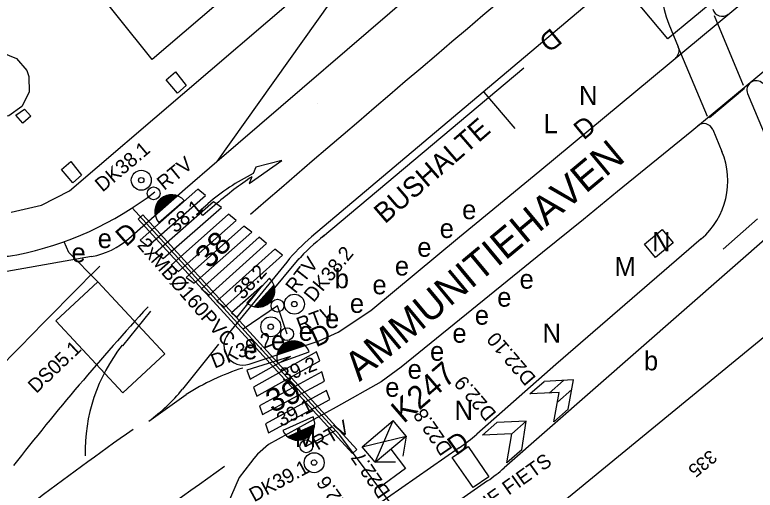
# Model space of a CAD drawing. Extents: x 81617 to 82144, y 454649 to 455150.
# Drawn here: x 81870.9 to 81909.62, y 454868.02 to 454892.85 of the extents above; entities that cross this region are included whole.
import ezdxf

# ---------------------------------------------------------------- set-up
doc = ezdxf.new("R2010")
doc.units = 0
for name, color, linetype in [('B-WE-OG-TOPOGRAFIE-G', 7, 'Continuous'), ('B-WE-VW-MARKERING-G', 7, 'Continuous'), ('N-OI-KL-VRI_KABEL_DETECTIE_SELECTIEF-G', 7, 'Continuous'), ('N-OI-KL-VRI_KABELGEUL-G', 7, 'Continuous'), ('N-OI-KL-VRI_LUS_DETECTIE-G', 7, 'Continuous'), ('N-OI-KL-VRI_LUS_DETECTIE-T18', 7, 'Continuous'), ('N-OI-KL-VRI_LUS_DETECTIE_SELECTIEF-G', 7, 'Continuous'), ('N-OI-KL-VRI_LUS_DETECTIE_SELECTIEF-T18', 7, 'Continuous'), ('N-OI-KL-VRI_MANTELBUIS-G', 7, 'Continuous'), ('N-OI-KL-VRI_MANTELBUIS-T18', 7, 'Continuous'), ('N-WE-VW-VRI_ARMATUUR-S', 7, 'Continuous'), ('N-WE-VW-VRI_ARMATUUR-T18', 7, 'Continuous'), ('N-WE-VW-VRI_KAST-S', 7, 'Continuous'), ('N-WE-VW-VRI_KAST-T25', 7, 'Continuous'), ('N-WE-VW-VRI_MAST-S', 7, 'Continuous'), ('N-WE-VW-VRI_RICHTINGNUMMER-T25', 7, 'Continuous')]:
    doc.layers.add(name, color=color, linetype=linetype)

msp = doc.modelspace()

# ---------------------------------------------------------------- linework, layer by layer
at = {"layer": 'B-WE-OG-TOPOGRAFIE-G'}
for p, q in [((81873.764, 454883.663), (81895.876, 454902.551)), ((81905.057, 454891.588), (81895.876, 454902.551)), ((81915.332, 454900.158), (81905.057, 454891.588)), ((81903.077, 454895.285), (81886.425, 454881.256)), ((81887.412, 454893.525), (81881.465, 454885.191)), ((81905.107, 454892.354), (81905.599, 454891.177)), ((81897.061, 454886.92), (81895.452, 454888.817)), ((81909.22, 454888.733), (81910.638, 454885.336)), ((81907.401, 454886.86), (81907.878, 454885.717)), ((81916.221, 454886.463), (81896.497, 454869.183)), ((81895.714, 454882.526), (81898.36, 454884.706)), ((81872.307, 454882.913), (81873.764, 454883.663)), ((81870.712, 454882.537), (81872.307, 454882.913)), ((81900.642, 454882.153), (81898.504, 454880.427)), ((81874.916, 454880.226), (81869.99, 454879.351)), ((81885.125, 454879.936), (81882.062, 454876.187)), ((81883.151, 454874.605), (81886.811, 454875.821)), ((81894.147, 454870.23), (81885.959, 454864.545))]:
    msp.add_line(p, q, dxfattribs=at)
for points in [[(81905.797, 454910.826), (81895.907, 454902.577), (81894.356, 454904.415), (81878.095, 454890.513), (81872.591, 454897.372), (81877.883, 454901.619), (81888.858, 454911.006), (81888.57, 454911.351)], [(81881.465, 454885.191), (81892.751, 454894.89), (81902.683, 454903.166)], [(81898.36, 454884.706), (81910.134, 454894.484), (81917.589, 454900.632)], [(81919.999, 454898.128), (81906.308, 454886.765), (81902.426, 454883.614), (81900.642, 454882.153)], [(81871.645, 454889.635), (81871.649, 454888.803), (81871.269, 454888.063), (81870.591, 454887.582), (81869.768, 454887.467), (81868.985, 454887.745), (81868.625, 454888.058), (81868.267, 454888.805), (81868.296, 454889.633), (81868.704, 454890.354), (81869.398, 454890.805), (81870.223, 454890.883), (81870.99, 454890.571), (81871.527, 454889.94), (81871.645, 454889.635)], [(81879.871, 454889.153), (81879.407, 454888.757), (81878.816, 454889.449), (81879.303, 454889.864), (81879.871, 454889.153)], [(81871.322, 454887.183), (81870.954, 454887.608), (81871.418, 454887.928), (81871.745, 454887.55), (81871.322, 454887.183)], [(81873.935, 454884.076), (81873.343, 454884.766), (81873.829, 454885.183), (81874.399, 454884.473), (81873.935, 454884.076)], [(81876.866, 454881.167), (81879.804, 454883.764), (81881.465, 454885.191)], [(81886.811, 454875.821), (81887.808, 454876.282), (81889.527, 454877.414), (81894.156, 454881.247), (81895.714, 454882.526)], [(81891.095, 454859.963), (81890.844, 454860.269), (81917.092, 454881.782)], [(81904.758, 454881.628), (81905.336, 454880.933), (81904.402, 454880.175), (81903.833, 454880.868), (81904.758, 454881.628)], [(81906.798, 454881.147), (81899.186, 454874.583), (81895.056, 454870.943)], [(81898.504, 454880.427), (81891.112, 454874.44), (81890.056, 454873.683), (81887.703, 454872.36), (81884.178, 454870.411), (81883.594, 454869.904), (81883.411, 454869.671)], [(81883.411, 454869.671), (81883.233, 454869.443)], [(81883.233, 454869.443), (81882.632, 454868.676), (81882.012, 454867.245), (81881.775, 454865.703), (81881.936, 454864.151), (81882.502, 454862.646)], [(81895.625, 454868.501), (81888.346, 454863.428)]]:
    msp.add_lwpolyline(points, dxfattribs=at)
for centre, radius, start, end in [((81909.721, 454894.281), 5, 129.9068, 202.6584), ((81907.892, 454893.272), 0.5, 194.9072, 309.7087), ((81905.137, 454890.984), 0.5, 309.7087, 22.6584), ((81909.674, 454888.918), 0.491, 45.0027, 202.1804), ((81906.939, 454886.668), 0.5, 22.6584, 129.6922), ((81904.187, 454884.176), 4, 310.7629, 22.6584), ((81874.217, 454884.164), 4, 280.0658, 311.4758), ((81892.868, 454873.608), 10, 130.1148, 140.7468), ((81882.836, 454875.554), 1, 140.7468, 288.3806), ((81888.443, 454878.444), 10, 304.7727, 311.399), ((81889.907, 454876.705), 10, 304.8723, 311.2203)]:
    msp.add_arc(centre, radius, start, end, dxfattribs=at)
at = {"layer": 'B-WE-VW-MARKERING-G'}
for p, q in [((81909.012, 454889.161), (81907.493, 454892.8)), ((81907.118, 454887.538), (81905.599, 454891.177)), ((81886.988, 454881.261), (81897.514, 454890.085)), ((81907.227, 454887.492), (81909.068, 454889.019)), ((81886.718, 454888.22), (81886.719, 454888.22)), ((81909.745, 454882.201), (81907.947, 454880.616)), ((81884.154, 454878.169), (81885.773, 454880.127)), ((81876.555, 454875.556), (81878.025, 454877.377)), ((81881.555, 454875.639), (81879.673, 454873.29)), ((81877.904, 454871.631), (81879.86, 454873.02))]:
    msp.add_line(p, q, dxfattribs=at)
for points in [[(81883.298, 454884.391), (81883.152, 454884.032), (81884.861, 454885.235), (81883.508, 454884.892), (81883.367, 454884.558)], [(81881.463, 454882.991), (81880.734, 454882.366), (81880.539, 454882.594), (81880.994, 454882.984)]]:
    msp.add_lwpolyline(points, dxfattribs=at)
for points in [[(81877.857, 454880.761), (81880.868, 454883.416), (81880.477, 454883.739), (81877.466, 454881.085)], [(81878.666, 454880.115), (81881.711, 454882.782), (81881.3, 454883.087), (81878.254, 454880.42)], [(81879.471, 454879.449), (81882.473, 454882.113), (81882.082, 454882.436), (81879.079, 454879.772)], [(81880.282, 454878.833), (81883.303, 454881.504), (81882.887, 454881.806), (81879.866, 454879.135)], [(81881.06, 454878.207), (81884.069, 454880.909), (81883.679, 454881.234), (81880.671, 454878.532)], [(81881.866, 454877.577), (81884.897, 454880.288), (81884.498, 454880.605), (81881.467, 454877.894)], [(81882.524, 454877.051), (81883.851, 454878.709), (81882.231, 454877.291)], [(81883.556, 454872.939), (81886.855, 454874.78), (81886.688, 454875.248), (81883.388, 454873.407)], [(81883.206, 454873.82), (81885.314, 454875.009), (81883.039, 454874.288)], [(81883.858, 454871.966), (81887.102, 454873.719), (81886.966, 454874.205), (81883.691, 454872.433)], [(81884.172, 454871.01), (81887.372, 454872.755), (81887.204, 454873.223), (81884.005, 454871.478)]]:
    msp.add_lwpolyline(points, close=True, dxfattribs=at)
for centre, radius, start, end in [((82917.127, 453685.631), 1581.531, 129.587403, 130.823582), ((81888.509, 454874.227), 11.54, 116.4593, 130.634), ((81894.5, 454867.798), 20.02, 124.0094, 130.634), ((81894.315, 454872.198), 11.647, 128.3994, 137.9113), ((82219.514, 454535.314), 486.895, 134.97926, 135.80708), ((81983.253, 454780.99), 142.962, 137.48788, 141.84973), ((81883.609, 454869.995), 9.033, 141.7483, 181.1781), ((81886.861, 454861.84), 13.191, 107.8383, 122.0585), ((81872.715, 454878.94), 8.964, 305.3706, 320.9237), ((81999.362, 454697.85), 212.13, 125.19968, 128.77534), ((82436.117, 454084.333), 960.875, 125.226465, 125.740356)]:
    msp.add_arc(centre, radius, start, end, dxfattribs=at)
at = {"layer": 'N-OI-KL-VRI_KABEL_DETECTIE_SELECTIEF-G'}
msp.add_line((81875.251, 454878.904), (81873.737, 454880.443), dxfattribs=at)
at = {"layer": 'N-OI-KL-VRI_KABELGEUL-G'}
msp.add_line((81886.146, 454870.311), (81887.671, 454871.144), dxfattribs=at)
for points in [[(81886.495, 454859.072), (81889.398, 454860.377), (81892.955, 454863.292), (81892.853, 454864.259), (81887.904, 454870.888), (81877.049, 454882.767)], [(81873.737, 454880.443), (81873.478, 454881)], [(81885.144, 454876.171), (81884.639, 454877.657), (81882.841, 454876.423)], [(81890.559, 454870.162), (81891.328, 454869.16), (81889.958, 454868.137)]]:
    msp.add_lwpolyline(points, dxfattribs=at)
for centre, radius, start, end in [((81867.653, 454897.27), 17.281, 281.1951, 307.7159), ((81870.263, 454883.584), 3.35, 223.0627, 282.8439)]:
    msp.add_arc(centre, radius, start, end, dxfattribs=at)
at = {"layer": 'N-OI-KL-VRI_LUS_DETECTIE-G'}
for p, q in [((81897.828, 454873.044), (81898.578, 454873.705)), ((81898.851, 454873.091), (81899.601, 454873.752)), ((81899.273, 454872.609), (81900.024, 454873.27)), ((81899.096, 454871.597), (81899.846, 454872.258)), ((81897.644, 454871.62), (81896.894, 454870.959)), ((81895.36, 454870.889), (81896.11, 454871.55)), ((81893.782, 454869.723), (81894.603, 454870.294)), ((81894.603, 454870.294), (81895.697, 454868.724)), ((81897.417, 454870.134), (81896.628, 454869.442)), ((81894.876, 454868.153), (81893.782, 454869.723)), ((81895.697, 454868.724), (81894.876, 454868.153))]:
    msp.add_line(p, q, dxfattribs=at)
for points in [[(81899.846, 454872.258), (81900.112, 454873.775), (81898.578, 454873.705)], [(81899.096, 454871.597), (81899.362, 454873.114), (81897.828, 454873.044)], [(81897.417, 454870.134), (81897.644, 454871.62), (81896.11, 454871.55)], [(81896.628, 454869.442), (81896.894, 454870.959), (81895.36, 454870.889)]]:
    msp.add_lwpolyline(points, dxfattribs=at)
at = {"layer": 'N-OI-KL-VRI_LUS_DETECTIE_SELECTIEF-G'}
for p, q in [((81875.251, 454878.904), (81873.056, 454876.859)), ((81878.756, 454875.14), (81875.251, 454878.904)), ((81873.056, 454876.859), (81876.561, 454873.096)), ((81876.561, 454873.096), (81878.756, 454875.14))]:
    msp.add_line(p, q, dxfattribs=at)
at = {"layer": 'N-OI-KL-VRI_MANTELBUIS-G'}
msp.add_lwpolyline([(81877.355, 454882.183), (81877.592, 454882.399), (81888.796, 454870.15), (81888.56, 454869.934), (81877.355, 454882.183)], dxfattribs=at)
at = {"layer": 'N-WE-VW-VRI_ARMATUUR-S'}
for p, q in [((81878.226, 454882.575), (81879.225, 454883.442)), ((81878.227, 454882.535), (81879.263, 454883.435)), ((81878.228, 454882.614), (81879.185, 454883.448)), ((81878.23, 454882.499), (81879.301, 454883.428)), ((81878.231, 454882.657), (81879.142, 454883.453)), ((81878.234, 454882.461), (81879.336, 454883.42)), ((81878.235, 454882.702), (81879.098, 454883.452)), ((81878.24, 454882.426), (81879.37, 454883.409)), ((81878.241, 454882.749), (81879.049, 454883.45)), ((81878.247, 454882.393), (81879.401, 454883.397)), ((81878.255, 454882.797), (81879, 454883.445)), ((81878.27, 454882.851), (81878.944, 454883.438)), ((81878.292, 454882.91), (81878.882, 454883.426)), ((81878.322, 454882.976), (81878.812, 454883.402)), ((81878.371, 454883.058), (81878.726, 454883.367)), ((81878.48, 454883.193), (81878.577, 454883.28)), ((81878.441, 454882.004), (81879.759, 454883.153)), ((81884.22, 454879.097), (81883.038, 454877.807)), ((81884.456, 454878.732), (81883.421, 454877.605)), ((81884.466, 454878.699), (81883.454, 454877.596)), ((81884.476, 454878.666), (81883.488, 454877.589)), ((81884.484, 454878.629), (81883.525, 454877.585)), ((81884.492, 454878.593), (81883.563, 454877.582)), ((81884.497, 454878.553), (81883.601, 454877.579)), ((81884.5, 454878.514), (81883.642, 454877.578)), ((81884.502, 454878.472), (81883.686, 454877.578)), ((81884.502, 454878.426), (81883.729, 454877.584)), ((81884.501, 454878.378), (81883.777, 454877.592)), ((81884.493, 454878.329), (81883.825, 454877.602)), ((81884.485, 454878.274), (81883.88, 454877.615)), ((81884.469, 454878.213), (81883.941, 454877.634)), ((81884.446, 454878.144), (81884.007, 454877.666)), ((81884.407, 454878.057), (81884.089, 454877.71)), ((81884.314, 454877.911), (81884.228, 454877.814)), ((81884.616, 454875.085), (81886.058, 454875.598)), ((81884.622, 454875.119), (81886.033, 454875.621)), ((81884.629, 454875.153), (81886.006, 454875.643)), ((81884.639, 454875.19), (81885.976, 454875.664)), ((81884.649, 454875.225), (81885.943, 454875.684)), ((81884.664, 454875.262), (81885.91, 454875.704)), ((81884.679, 454875.298), (81885.875, 454875.725)), ((81884.697, 454875.337), (81885.837, 454875.745)), ((81884.718, 454875.377), (81885.795, 454875.76)), ((81884.741, 454875.419), (81885.749, 454875.776)), ((81884.772, 454875.459), (81885.702, 454875.789)), ((81884.805, 454875.503), (81885.647, 454875.803)), ((81884.848, 454875.55), (81885.585, 454875.815)), ((81884.9, 454875.601), (81885.511, 454875.818)), ((81884.974, 454875.659), (81885.418, 454875.817)), ((81885.126, 454875.745), (81885.247, 454875.79)), ((81884.654, 454874.653), (81886.302, 454875.24)), ((81886.509, 454871.854), (81884.913, 454871.14)), ((81886.581, 454871.426), (81885.184, 454870.802)), ((81886.578, 454871.392), (81885.211, 454870.781)), ((81886.574, 454871.357), (81885.24, 454870.761)), ((81886.566, 454871.32), (81885.271, 454870.742)), ((81886.559, 454871.284), (81885.305, 454870.725)), ((81886.548, 454871.246), (81885.339, 454870.707)), ((81886.535, 454871.208), (81885.377, 454870.69)), ((81886.52, 454871.169), (81885.416, 454870.672)), ((81886.502, 454871.127), (81885.459, 454870.661)), ((81886.482, 454871.083), (81885.506, 454870.649)), ((81886.455, 454871.041), (81885.554, 454870.639)), ((81886.426, 454870.994), (81885.609, 454870.63)), ((81886.387, 454870.944), (81885.673, 454870.623)), ((81886.339, 454870.89), (81885.746, 454870.625)), ((81886.269, 454870.825), (81885.839, 454870.633)), ((81886.125, 454870.728), (81886.007, 454870.673))]:
    msp.add_line(p, q, dxfattribs=at)
for centre, radius in [((81877.519, 454884.21), 0.522), ((81877.514, 454884.214), 0.141), ((81885.524, 454877.735), 0.522), ((81885.519, 454877.738), 0.141), ((81884.292, 454876.552), 0.522), ((81884.287, 454876.555), 0.141), ((81886.556, 454869.456), 0.522), ((81886.551, 454869.459), 0.141)]:
    msp.add_circle(centre, radius, dxfattribs=at)
for centre, start, end in [((81879.1, 454882.578), 41.0181, 221.0181), ((81883.629, 454878.452), 227.456, 47.456), ((81885.478, 454874.946), 19.5786, 199.5786), ((81885.711, 454871.497), 204.0669, 24.0669)]:
    msp.add_arc(centre, 0.873, start, end, dxfattribs=at)
at = {"layer": 'N-WE-VW-VRI_KAST-S'}
for p, q in [((81889.062, 454870.287), (81890.686, 454871.659)), ((81889.748, 454869.478), (81890.687, 454871.66)), ((81891.371, 454870.846), (81890.687, 454871.66)), ((81889.062, 454870.287), (81891.371, 454870.846)), ((81889.748, 454869.478), (81891.371, 454870.846)), ((81891.371, 454870.846), (81891.195, 454869.802)), ((81889.748, 454869.478), (81889.062, 454870.287)), ((81890.81, 454869.475), (81889.748, 454869.478))]:
    msp.add_line(p, q, dxfattribs=at)
at = {"layer": 'N-WE-VW-VRI_MAST-S'}
for centre in [(81878.165, 454883.523), (81884.639, 454877.657), (81885.144, 454876.171), (81886.146, 454870.311)]:
    msp.add_circle(centre, 0.335, dxfattribs=at)

# ---------------------------------------------------------------- texts
at = {"layer": 'B-WE-OG-TOPOGRAFIE-G'}
for s, height, rotation, p in [('D', 1, 219.6608, (81898.965, 454892.204)), ('BUSHALTE', 1.05, 40.9275, (81890.255, 454881.899)), ('D', 1, 39.6369, (81900.65, 454886.277)), ('AMMUNITIEHAVEN', 1.5, 39.7166, (81888.929, 454873.659)), ('D', 1, 41.3545, (81876.72, 454880.698)), ('D', 1, 24.5199, (81886.656, 454875.471)), ('D', 1, 35.6416, (81893.984, 454869.8)), ('335', 0.7, 219.3386, (81907.26, 454870.168))]:
    msp.add_text(s, height=height, rotation=rotation, dxfattribs=at).set_placement(p)
for s, p in [('N', (81900.405, 454888.141)), ('L', (81898.559, 454886.668)), ('e', (81894.294, 454882.174)), ('e', (81893.122, 454881.193)), ('e', (81875.238, 454880.667)), ('N', (81904.228, 454880.5)), ('e', (81891.949, 454880.213)), ('e', (81873.87, 454879.928)), ('M', (81902.262, 454879.208)), ('e', (81890.777, 454879.232)), ('b', (81887.633, 454878.569)), ('e', (81889.605, 454878.252)), ('e', (81897.299, 454878.546)), ('e', (81896.128, 454877.605)), ('e', (81888.425, 454877.28)), ('e', (81894.957, 454876.664)), ('e', (81887.128, 454876.481)), ('N', (81898.5, 454875.723)), ('e', (81885.749, 454875.823)), ('e', (81893.786, 454875.722)), ('e', (81884.3, 454875.339)), ('e', (81882.85, 454874.855)), ('e', (81892.616, 454874.781)), ('b', (81903.8, 454874.279)), ('e', (81891.445, 454873.84)), ('e', (81890.274, 454872.899)), ('N', (81893.895, 454871.694)), ('M', (81885.55, 454870.271))]:
    msp.add_text(s, height=1, dxfattribs=at).set_placement(p)
at = {"layer": 'N-OI-KL-VRI_LUS_DETECTIE-T18'}
for s, rotation, p in [('D22.10', 130.5652, (81898.196, 454873.894)), ('D22.9', 130.5652, (81896.13, 454872.038)), ('D22.8', 124.4022, (81893.821, 454870.166)), ('D22.7', 124.4022, (81890.572, 454867.928)), ('TESTDETECTIE FIETS', 35.3937, (81890.371, 454863.214)), ('D22.6', 124.4022, (81888.76, 454866.634))]:
    msp.add_text(s, height=0.75, rotation=rotation, dxfattribs=at).set_placement(p)
at = {"layer": 'N-OI-KL-VRI_LUS_DETECTIE_SELECTIEF-T18'}
msp.add_text('DS05.1', height=0.75, rotation=43.6584, dxfattribs=at).set_placement((81872.023, 454873.04))
at = {"layer": 'N-OI-KL-VRI_MANTELBUIS-T18'}
msp.add_text('2xMB%%C160PVC', height=0.75, rotation=311.22, dxfattribs=at).set_placement((81877.272, 454880.797))
at = {"layer": 'N-WE-VW-VRI_ARMATUUR-S'}
for rotation, p in [(39.3238, (81878.718, 454883.65)), (52.0106, (81885.581, 454878.247)), (20.2839, (81885.804, 454876.281)), (29.8567, (81886.734, 454870.08))]:
    msp.add_text('RTV', height=0.75, rotation=rotation, dxfattribs=at).set_placement(p)
at = {"layer": 'N-WE-VW-VRI_ARMATUUR-T18'}
for s, rotation, p in [('DK38.1', 40.1521, (81875.488, 454883.56)), ('38.1', 40.1521, (81879.3, 454881.422)), ('DK38.2', 50.3575, (81886.527, 454877.79)), ('38.2', 47.8779, (81882.825, 454877.934)), ('DK39.2', 21.8905, (81881.347, 454874.366)), ('39.2', 21.2479, (81884.951, 454873.614)), ('39.1', 26.155, (81884.828, 454871.316)), ('DK39.1', 28.5657, (81883.422, 454867.381))]:
    msp.add_text(s, height=0.75, rotation=rotation, dxfattribs=at).set_placement(p)
at = {"layer": 'N-WE-VW-VRI_KAST-T25'}
msp.add_text('K247', height=1.2, rotation=40.7326, dxfattribs=at).set_placement((81891.237, 454871.467))
at = {"layer": 'N-WE-VW-VRI_RICHTINGNUMMER-T25'}
for s, rotation, p in [('38', 46.3121, (81881.083, 454879.543)), ('39', 22.9926, (81884.35, 454872.043))]:
    msp.add_text(s, height=1.2, rotation=rotation, dxfattribs=at).set_placement(p)

doc.saveas('drawing.dxf')
